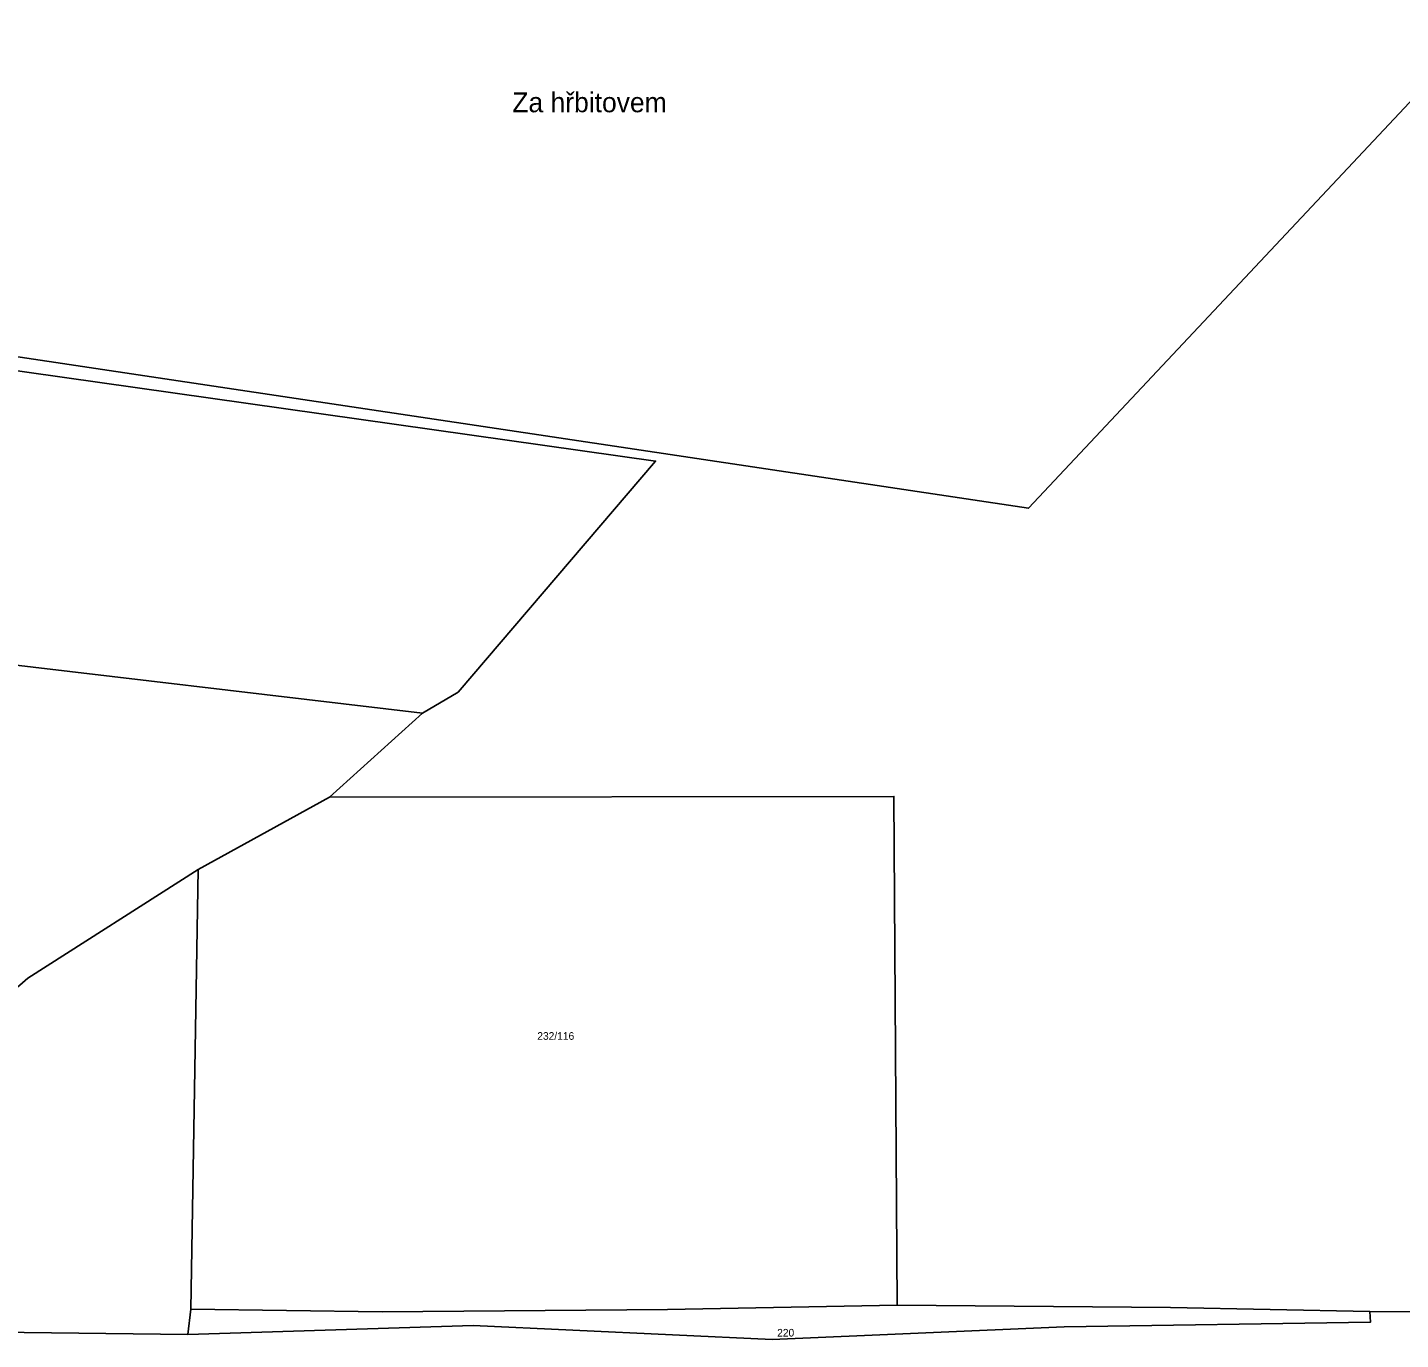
# Model space of a CAD drawing. Extents: x -887272 to -880188, y -1026687 to -1021896.
# Drawn here: x -882638.7 to -882333.3, y -1024046.9 to -1023755.1 of the extents above; entities that cross this region are included whole.
import ezdxf

# ---------------------------------------------------------------- set-up
doc = ezdxf.new("R2010")
doc.units = 0
for name, color, linetype in [('Hranice parcel', 7, 'Continuous'), ('Parcelní čísla', 7, 'Continuous'), ('Pop  PČ popisy', 7, 'Continuous')]:
    doc.layers.add(name, color=color, linetype=linetype)

msp = doc.modelspace()

# ---------------------------------------------------------------- linework, layer by layer
at = {"layer": 'Hranice parcel'}
for p, q in [((-882550.84, -1023907.6), (-882571.48, -1023926.26)), ((-882600.7, -1023942.36), (-882571.48, -1023926.26)), ((-882602.37, -1024040.09), (-882600.7, -1023942.36)), ((-882603.02, -1024045.76), (-882602.37, -1024040.09)), ((-882384.42, -1024039.73), (-882445.26, -1024039.2)), ((-882340.1, -1024040.68), (-882384.42, -1024039.73)), ((-882680.86, -1024044.8), (-882603.02, -1024045.76))]:
    msp.add_line(p, q, dxfattribs=at)
for points in [[(-882058.02, -1023479.44), (-882103.84, -1023528.65), (-882178.79, -1023609.12), (-882251.38, -1023686.73), (-882326.67, -1023766.9), (-882416, -1023862), (-882806.28, -1023803.54), (-882785.58, -1023775.53)], [(-882814.51, -1023804.61), (-882721.64, -1023820.02), (-882498.98, -1023851.5), (-882542.88, -1023902.92), (-882550.84, -1023907.6)], [(-882740.58, -1023885.14), (-882655.04, -1023895.24), (-882550.84, -1023907.6)], [(-882571.48, -1023926.26), (-882445.96, -1023926.09), (-882445.26, -1024039.2)], [(-882600.7, -1023942.36), (-882638.58, -1023966.48), (-882653.18, -1023979.16), (-882692.14, -1023993.26)], [(-882340.1, -1024040.68), (-882291.8, -1024041.02), (-882266.44, -1024041.52), (-882231.92, -1024039.84), (-882208.92, -1024035.12), (-882179.22, -1024022.58), (-882174.49, -1024020.26)], [(-882603.02, -1024045.76), (-882539.56, -1024043.76), (-882473.06, -1024046.88), (-882408.1, -1024044.08), (-882339.94, -1024043.02), (-882340.1, -1024040.68)], [(-882445.26, -1024039.2), (-882496.32, -1024040.18), (-882559.82, -1024040.7), (-882602.37, -1024040.09)]]:
    msp.add_lwpolyline(points, dxfattribs=at)

# ---------------------------------------------------------------- texts
at = {"layer": 'Parcelní čísla'}
for s, p in [('232/116', (-882525.28, -1023980.22)), ('220', (-882471.92, -1024046.22))]:
    msp.add_text(s, height=1.7, dxfattribs=at).set_placement(p)
at = {"layer": 'Pop  PČ popisy'}
msp.add_text('Za hřbitovem', height=4.4, dxfattribs=at).set_placement((-882530.83, -1023773.93))

doc.saveas('drawing.dxf')
